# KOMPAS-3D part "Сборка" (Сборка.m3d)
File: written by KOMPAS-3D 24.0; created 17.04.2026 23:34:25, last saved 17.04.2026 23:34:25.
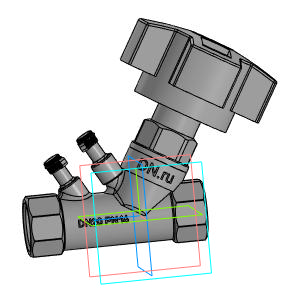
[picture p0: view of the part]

Document properties: Автор: tyuri; Полное имя файла: D:\Аутсорс\VB0000P-T Клапан балансировочный статический DN.ru\DN20\Исходные файлы\Сборка.m3d

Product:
- Part/product: Сборка
    Масса: 0.968314

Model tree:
1. Перпендикулярная плоскость:1
     Координата X = 40
2. Операция без истории:1

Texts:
  Точка начала. Х
  Точка начала. Y
  Точка начала. Z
